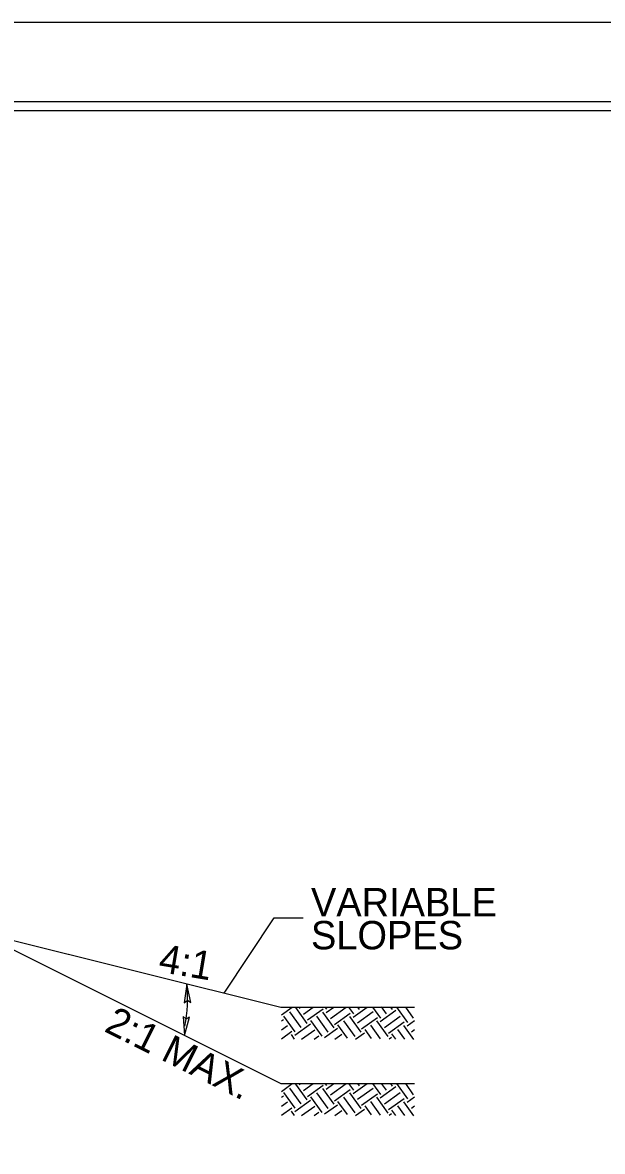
# Model space of a CAD drawing. Extents: x 3025871 to 3026431, y 707165 to 707825.
# Drawn here: x 3026216.82 to 3026241.49, y 707687.3 to 707735.34 of the extents above; entities that cross this region are included whole.
import ezdxf

# ---------------------------------------------------------------- set-up
doc = ezdxf.new("R2010")
doc.units = 0
for name, color, linetype in [('Old_Level_39', 7, 'Continuous'), ('Prop Drainage Structure Junction Box with Slab Lid TB 840 34 CELL', 7, 'Continuous'), ('Sheet Cutting Line CELL', 7, 'Continuous'), ('Typical Guardrail CELL', 7, 'Continuous'), ('Typical Terminator CELL', 7, 'Continuous'), ('Typical Text Centerline CELL', 7, 'Continuous'), ('Typical Text Grade Point CELL', 7, 'Continuous')]:
    doc.layers.add(name, color=color, linetype=linetype)

msp = doc.modelspace()

# ---------------------------------------------------------------- linework, layer by layer
at = {"layer": 'Old_Level_39'}
msp.add_lwpolyline([(3026273.948, 707731.968), (3026023.973, 707731.968), (3026023.973, 707573.703), (3026273.948, 707573.703)], close=True, dxfattribs=at)
at = {"layer": 'Prop Drainage Structure Junction Box with Slab Lid TB 840 34 CELL'}
for p, q in [((3026225.391, 707694.041), (3026227.518, 707697.244)), ((3026227.518, 707697.244), (3026228.76, 707697.244))]:
    msp.add_line(p, q, dxfattribs=at)
msp.add_arc((3026217.722, 707693.788), 6.116, 349.0804, 5.9845, dxfattribs=at)
at = {"layer": 'Sheet Cutting Line CELL'}
msp.add_lwpolyline([(3026272.073, 707731.586), (3026047.073, 707731.586), (3026047.073, 707574.086), (3026272.073, 707574.086)], close=True, dxfattribs=at)
at = {"layer": 'Typical Guardrail CELL'}
msp.add_line((3026214.811, 707696.686), (3026227.811, 707690.186), dxfattribs=at)
at = {"layer": 'Typical Terminator CELL'}
msp.add_lwpolyline([(3026274.623, 707735.336), (3026022.023, 707735.336), (3026022.023, 707570.336), (3026274.623, 707570.336)], close=True, dxfattribs=at)
at = {"layer": 'Typical Text Centerline CELL'}
for points in [[(3026223.976, 707693.643), (3026223.804, 707694.425), (3026223.7, 707693.625), (3026223.836, 707693.733)], [(3026223.652, 707693.039), (3026223.706, 707692.239), (3026223.928, 707693.014), (3026223.778, 707692.929)]]:
    msp.add_lwpolyline(points, close=True, dxfattribs=at)
at = {"layer": 'Typical Text Grade Point CELL'}
for p, q in [((3026214.811, 707696.686), (3026227.811, 707693.436)), ((3026227.811, 707693.436), (3026233.496, 707693.436)), ((3026227.811, 707693.436), (3026233.496, 707693.436)), ((3026227.833, 707693.107), (3026228.293, 707693.437)), ((3026227.833, 707693.107), (3026228.293, 707693.437)), ((3026228.673, 707692.57), (3026228.192, 707693.238)), ((3026228.673, 707692.57), (3026228.192, 707693.238)), ((3026228.923, 707692.75), (3026228.443, 707693.419)), ((3026228.923, 707692.75), (3026228.443, 707693.419)), ((3026228.586, 707693.395), (3026228.647, 707693.438)), ((3026228.586, 707693.395), (3026228.647, 707693.438)), ((3026228.767, 707693.144), (3026229.178, 707693.44)), ((3026228.767, 707693.144), (3026229.178, 707693.44)), ((3026228.947, 707692.894), (3026229.615, 707693.374)), ((3026228.947, 707692.894), (3026229.615, 707693.374)), ((3026230.072, 707692.562), (3026229.592, 707693.23)), ((3026230.072, 707692.562), (3026229.592, 707693.23)), ((3026229.759, 707693.351), (3026229.693, 707693.441)), ((3026229.759, 707693.351), (3026229.693, 707693.441)), ((3026229.735, 707693.207), (3026230.063, 707693.442)), ((3026229.735, 707693.207), (3026230.063, 707693.442)), ((3026229.915, 707692.956), (3026230.584, 707693.437)), ((3026229.915, 707692.956), (3026230.584, 707693.437)), ((3026230.095, 707692.706), (3026230.764, 707693.186)), ((3026230.095, 707692.706), (3026230.764, 707693.186)), ((3026230.907, 707693.162), (3026230.705, 707693.444)), ((3026230.907, 707693.162), (3026230.705, 707693.444)), ((3026230.884, 707693.019), (3026231.479, 707693.446)), ((3026230.884, 707693.019), (3026231.479, 707693.446)), ((3026231.064, 707692.768), (3026231.732, 707693.249)), ((3026231.064, 707692.768), (3026231.732, 707693.249)), ((3026231.158, 707693.343), (3026231.084, 707693.445)), ((3026231.158, 707693.343), (3026231.084, 707693.445)), ((3026232.056, 707692.974), (3026231.724, 707693.436)), ((3026232.056, 707692.974), (3026231.724, 707693.436)), ((3026232.033, 707692.831), (3026232.701, 707693.311)), ((3026232.033, 707692.831), (3026232.701, 707693.311)), ((3026232.307, 707693.155), (3026232.096, 707693.448)), ((3026232.307, 707693.155), (3026232.096, 707693.448)), ((3026232.557, 707693.335), (3026232.484, 707693.436)), ((3026232.557, 707693.335), (3026232.484, 707693.436)), ((3026233.205, 707692.786), (3026232.738, 707693.436)), ((3026233.205, 707692.786), (3026232.738, 707693.436)), ((3026233.455, 707692.966), (3026233.118, 707693.436)), ((3026233.455, 707692.966), (3026233.118, 707693.436)), ((3026227.833, 707692.854), (3026227.918, 707692.915)), ((3026227.833, 707692.854), (3026227.918, 707692.915)), ((3026227.833, 707692.473), (3026228.098, 707692.664)), ((3026227.833, 707692.473), (3026228.098, 707692.664)), ((3026228.422, 707692.39), (3026227.942, 707693.058)), ((3026228.422, 707692.39), (3026227.942, 707693.058)), ((3026228.398, 707692.246), (3026229.067, 707692.727)), ((3026228.398, 707692.246), (3026229.067, 707692.727)), ((3026229.571, 707692.202), (3026229.09, 707692.87)), ((3026229.571, 707692.202), (3026229.09, 707692.87)), ((3026229.821, 707692.382), (3026229.341, 707693.05)), ((3026229.821, 707692.382), (3026229.341, 707693.05)), ((3026230.64, 707692.125), (3026230.239, 707692.682)), ((3026230.64, 707692.125), (3026230.239, 707692.682)), ((3026230.97, 707692.194), (3026230.49, 707692.862)), ((3026230.97, 707692.194), (3026230.49, 707692.862)), ((3026231.221, 707692.374), (3026230.74, 707693.042)), ((3026231.221, 707692.374), (3026230.74, 707693.042)), ((3026231.244, 707692.518), (3026231.913, 707692.998)), ((3026231.244, 707692.518), (3026231.913, 707692.998)), ((3026232.054, 707692.096), (3026231.638, 707692.674)), ((3026232.054, 707692.096), (3026231.638, 707692.674)), ((3026232.369, 707692.186), (3026231.889, 707692.854)), ((3026232.369, 707692.186), (3026231.889, 707692.854)), ((3026232.213, 707692.58), (3026232.881, 707693.06)), ((3026232.213, 707692.58), (3026232.881, 707693.06)), ((3026232.393, 707692.33), (3026233.061, 707692.81)), ((3026232.393, 707692.33), (3026233.061, 707692.81)), ((3026233.468, 707692.068), (3026233.038, 707692.666)), ((3026233.468, 707692.068), (3026233.038, 707692.666)), ((3026233.181, 707692.643), (3026233.496, 707692.869)), ((3026233.181, 707692.643), (3026233.496, 707692.869)), ((3026227.833, 707692.093), (3026228.278, 707692.413)), ((3026227.833, 707692.093), (3026228.278, 707692.413)), ((3026228.394, 707692.076), (3026228.255, 707692.27)), ((3026228.394, 707692.076), (3026228.255, 707692.27)), ((3026228.691, 707692.076), (3026229.247, 707692.476)), ((3026228.691, 707692.076), (3026229.247, 707692.476)), ((3026229.219, 707692.076), (3026229.427, 707692.225)), ((3026229.219, 707692.076), (3026229.427, 707692.225)), ((3026229.667, 707692.144), (3026230.215, 707692.539)), ((3026229.667, 707692.144), (3026230.215, 707692.539)), ((3026230.101, 707692.076), (3026230.396, 707692.288)), ((3026230.101, 707692.076), (3026230.396, 707692.288)), ((3026230.983, 707692.076), (3026231.364, 707692.35)), ((3026230.983, 707692.076), (3026231.364, 707692.35)), ((3026231.668, 707692.104), (3026231.388, 707692.494)), ((3026231.668, 707692.104), (3026231.388, 707692.494)), ((3026232.696, 707692.083), (3026232.536, 707692.306)), ((3026232.696, 707692.083), (3026232.536, 707692.306)), ((3026233.082, 707692.076), (3026232.787, 707692.486)), ((3026233.082, 707692.076), (3026232.787, 707692.486)), ((3026233.361, 707692.392), (3026233.496, 707692.489)), ((3026233.361, 707692.392), (3026233.496, 707692.489)), ((3026232.411, 707692.089), (3026232.513, 707692.162)), ((3026232.411, 707692.089), (3026232.513, 707692.162)), ((3026227.811, 707690.186), (3026233.496, 707690.186)), ((3026227.811, 707690.186), (3026233.496, 707690.186)), ((3026227.833, 707689.857), (3026228.293, 707690.187)), ((3026227.833, 707689.857), (3026228.293, 707690.187)), ((3026228.422, 707689.14), (3026227.942, 707689.808)), ((3026228.422, 707689.14), (3026227.942, 707689.808)), ((3026228.673, 707689.32), (3026228.192, 707689.988)), ((3026228.673, 707689.32), (3026228.192, 707689.988)), ((3026228.923, 707689.5), (3026228.443, 707690.169)), ((3026228.923, 707689.5), (3026228.443, 707690.169)), ((3026228.586, 707690.145), (3026228.647, 707690.188)), ((3026228.586, 707690.145), (3026228.647, 707690.188)), ((3026228.767, 707689.894), (3026229.178, 707690.19)), ((3026228.767, 707689.894), (3026229.178, 707690.19)), ((3026228.947, 707689.644), (3026229.615, 707690.124)), ((3026228.947, 707689.644), (3026229.615, 707690.124)), ((3026229.821, 707689.132), (3026229.341, 707689.8)), ((3026229.821, 707689.132), (3026229.341, 707689.8)), ((3026230.072, 707689.312), (3026229.592, 707689.98)), ((3026230.072, 707689.312), (3026229.592, 707689.98)), ((3026229.759, 707690.101), (3026229.693, 707690.191)), ((3026229.759, 707690.101), (3026229.693, 707690.191)), ((3026229.735, 707689.957), (3026230.063, 707690.192)), ((3026229.735, 707689.957), (3026230.063, 707690.192)), ((3026229.915, 707689.706), (3026230.584, 707690.187)), ((3026229.915, 707689.706), (3026230.584, 707690.187)), ((3026230.095, 707689.456), (3026230.764, 707689.936)), ((3026230.095, 707689.456), (3026230.764, 707689.936)), ((3026230.907, 707689.912), (3026230.705, 707690.194)), ((3026230.907, 707689.912), (3026230.705, 707690.194)), ((3026231.221, 707689.124), (3026230.74, 707689.792)), ((3026231.221, 707689.124), (3026230.74, 707689.792)), ((3026230.884, 707689.769), (3026231.479, 707690.196)), ((3026230.884, 707689.769), (3026231.479, 707690.196)), ((3026231.064, 707689.518), (3026231.732, 707689.999)), ((3026231.064, 707689.518), (3026231.732, 707689.999)), ((3026231.158, 707690.093), (3026231.084, 707690.195)), ((3026231.158, 707690.093), (3026231.084, 707690.195)), ((3026232.056, 707689.724), (3026231.724, 707690.186)), ((3026232.056, 707689.724), (3026231.724, 707690.186)), ((3026232.033, 707689.581), (3026232.701, 707690.061)), ((3026232.033, 707689.581), (3026232.701, 707690.061)), ((3026232.307, 707689.905), (3026232.096, 707690.198)), ((3026232.307, 707689.905), (3026232.096, 707690.198)), ((3026232.213, 707689.33), (3026232.881, 707689.81)), ((3026232.213, 707689.33), (3026232.881, 707689.81)), ((3026232.557, 707690.085), (3026232.484, 707690.186)), ((3026232.557, 707690.085), (3026232.484, 707690.186)), ((3026233.205, 707689.536), (3026232.738, 707690.186)), ((3026233.205, 707689.536), (3026232.738, 707690.186)), ((3026233.455, 707689.716), (3026233.118, 707690.186)), ((3026233.455, 707689.716), (3026233.118, 707690.186)), ((3026227.833, 707689.604), (3026227.918, 707689.665)), ((3026227.833, 707689.604), (3026227.918, 707689.665)), ((3026227.833, 707689.223), (3026228.098, 707689.414)), ((3026227.833, 707689.223), (3026228.098, 707689.414)), ((3026228.398, 707688.996), (3026229.067, 707689.477)), ((3026228.398, 707688.996), (3026229.067, 707689.477)), ((3026229.571, 707688.952), (3026229.09, 707689.62)), ((3026229.571, 707688.952), (3026229.09, 707689.62)), ((3026229.667, 707688.894), (3026230.215, 707689.289)), ((3026229.667, 707688.894), (3026230.215, 707689.289)), ((3026230.64, 707688.875), (3026230.239, 707689.432)), ((3026230.64, 707688.875), (3026230.239, 707689.432)), ((3026230.97, 707688.944), (3026230.49, 707689.612)), ((3026230.97, 707688.944), (3026230.49, 707689.612)), ((3026231.244, 707689.268), (3026231.913, 707689.748)), ((3026231.244, 707689.268), (3026231.913, 707689.748)), ((3026232.054, 707688.846), (3026231.638, 707689.424)), ((3026232.054, 707688.846), (3026231.638, 707689.424)), ((3026232.369, 707688.936), (3026231.889, 707689.604)), ((3026232.369, 707688.936), (3026231.889, 707689.604)), ((3026232.393, 707689.08), (3026233.061, 707689.56)), ((3026232.393, 707689.08), (3026233.061, 707689.56)), ((3026233.468, 707688.818), (3026233.038, 707689.416)), ((3026233.468, 707688.818), (3026233.038, 707689.416)), ((3026233.181, 707689.393), (3026233.496, 707689.619)), ((3026233.181, 707689.393), (3026233.496, 707689.619)), ((3026227.833, 707688.843), (3026228.278, 707689.163)), ((3026227.833, 707688.843), (3026228.278, 707689.163)), ((3026228.394, 707688.826), (3026228.255, 707689.02)), ((3026228.394, 707688.826), (3026228.255, 707689.02)), ((3026228.691, 707688.826), (3026229.247, 707689.226)), ((3026228.691, 707688.826), (3026229.247, 707689.226)), ((3026229.219, 707688.826), (3026229.427, 707688.975)), ((3026229.219, 707688.826), (3026229.427, 707688.975)), ((3026230.101, 707688.826), (3026230.396, 707689.038)), ((3026230.101, 707688.826), (3026230.396, 707689.038)), ((3026230.983, 707688.826), (3026231.364, 707689.1)), ((3026230.983, 707688.826), (3026231.364, 707689.1)), ((3026231.668, 707688.854), (3026231.388, 707689.244)), ((3026231.668, 707688.854), (3026231.388, 707689.244)), ((3026232.411, 707688.839), (3026232.513, 707688.912)), ((3026232.411, 707688.839), (3026232.513, 707688.912)), ((3026232.696, 707688.833), (3026232.536, 707689.056)), ((3026232.696, 707688.833), (3026232.536, 707689.056)), ((3026233.082, 707688.826), (3026232.787, 707689.236)), ((3026233.082, 707688.826), (3026232.787, 707689.236)), ((3026233.361, 707689.142), (3026233.496, 707689.239)), ((3026233.361, 707689.142), (3026233.496, 707689.239))]:
    msp.add_line(p, q, dxfattribs=at)

# ---------------------------------------------------------------- texts
for s, p in [('VARIABLE', (3026229.09, 707697.302)), ('SLOPES', (3026229.09, 707695.9))]:
    msp.add_text(s, height=1.2089, dxfattribs=at).set_placement(p)
for s, rotation, p in [('4:1', 350.5377, (3026222.564, 707694.949)), ('2:1 MAX.', 333.428, (3026220.248, 707692.433))]:
    msp.add_text(s, height=1.2089, rotation=rotation, dxfattribs=at).set_placement(p)

doc.saveas('drawing.dxf')
